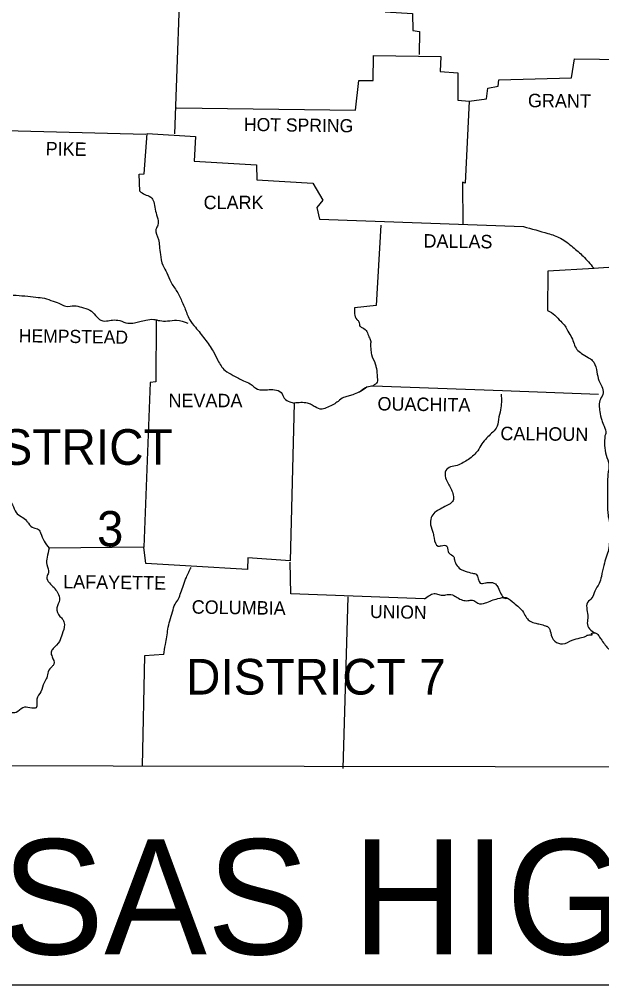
# Model space of a CAD drawing. Extents: x -2512 to 3792, y -435 to 2624.
# Drawn here: x 2800 to 2982.2, y 1364.9 to 1667 of the extents above; entities that cross this region are included whole.
import ezdxf

# ---------------------------------------------------------------- set-up
doc = ezdxf.new("R2010")
doc.units = 0
for name, color, linetype in [('1', 7, 'Continuous'), ('2', 7, 'Continuous'), ('3', 7, 'Continuous')]:
    doc.layers.add(name, color=color, linetype=linetype)

msp = doc.modelspace()

# ---------------------------------------------------------------- linework, layer by layer
at = {"layer": '1'}
for points in [[(2891.27, 1695.97), (2903.11, 1695.09), (2903.5, 1682.76), (2901.83, 1682.17), (2901.64, 1675.62), (2914.46, 1674.74), (2914.46, 1669.35), (2922.97, 1668.86), (2923.07, 1663.48), (2925.12, 1663.19), (2925.02, 1655.95)], [(2850.76, 1692.15), (2848.51, 1631.2)], [(2849.2, 1639.32), (2905.16, 1638.53), (2906.24, 1647.83), (2910.64, 1647.83), (2910.74, 1655.66), (2931.87, 1655.36), (2931.68, 1650.67), (2937.16, 1650.27), (2937.16, 1641.66), (2940.68, 1641.37)], [(2940.68, 1641.37), (2946.16, 1642.15), (2946.55, 1645.48), (2949.78, 1646.07), (2949.97, 1648.02), (2972.77, 1648.71), (2973.65, 1654.68), (2997.03, 1654.29)], [(2940.68, 1641.37), (2939.5, 1615.74), (2938.62, 1616.03), (2938.72, 1602.72)], [(2783.55, 1632.57), (2839.51, 1631.1)], [(2837.65, 1613.19), (2837.46, 1618.57), (2839.02, 1618.67), (2840, 1631.29), (2855.07, 1630.32), (2854.68, 1622.59), (2874.15, 1621.51), (2874.24, 1616.81), (2891.85, 1615.74), (2894.89, 1610.45), (2893.03, 1608.11), (2893.91, 1604.49), (2957.7, 1602.14)], [(2913.09, 1602.63), (2911.62, 1577.48), (2904.87, 1576.7)], [(2993.9, 1589.91), (2979.62, 1589.03)], [(2979.81, 1589.03), (2965.33, 1588.15), (2965.24, 1575.92)], [(2842.84, 1572.98), (2842.64, 1553.51), (2840.88, 1553.31), (2838.92, 1501.75)], [(2910.64, 1552.34), (2951.15, 1550.87), (2981.18, 1549.69)], [(2885.98, 1546.86), (2884.71, 1497.55), (2871.5, 1498.43), (2871.41, 1494.81), (2853.79, 1495.88)], [(2769.26, 1512.61), (2769.46, 1433.46), (3128.04, 1432.87)], [(2853.79, 1495.88), (2839.61, 1496.67), (2838.92, 1501.75), (2809.28, 1501.46)], [(2926.69, 1485.61), (2884.91, 1487.17), (2884.71, 1497.06)], [(2902.72, 1486.29), (2901.15, 1432.58)], [(2845.18, 1468.19), (2839.12, 1467.8), (2838.43, 1433.36)]]:
    msp.add_lwpolyline(points, dxfattribs=at)
for points in [[(2837.65, 1613.19), (2839.22, 1612.21), (2841.08, 1611.33), (2842.05, 1609.87), (2842.45, 1607.62), (2843.13, 1605.17), (2843.33, 1602.63), (2842.74, 1601.26), (2843.52, 1598.13), (2843.82, 1595.97), (2844.11, 1593.43), (2844.89, 1590.01), (2846.16, 1587.66), (2847.34, 1584.82), (2849.29, 1581.79), (2850.96, 1578.46), (2851.74, 1576.7), (2853.21, 1573.08), (2855.07, 1570.63), (2858, 1566.91), (2860.64, 1563.1), (2862.11, 1560.26), (2864.36, 1557.13), (2866.91, 1555.57), (2870.13, 1553.9), (2872.19, 1552.92), (2874.54, 1551.26), (2877.57, 1551.06), (2879.82, 1551.06), (2881.88, 1550.18), (2882.85, 1548.42), (2884.61, 1547.25), (2885.98, 1546.86)], [(2957.7, 1602.14), (2965.33, 1599.98), (2969.25, 1598.52), (2973.16, 1595.68), (2976.39, 1592.84), (2979.62, 1589.22)], [(2798.03, 1580.71), (2801.74, 1580.42), (2805.17, 1580.03), (2807.81, 1579.73), (2810.55, 1578.75), (2813, 1577.87), (2814.56, 1577.19), (2817.2, 1577.38), (2819.45, 1576.89), (2822, 1576.01), (2823.86, 1574.35), (2825.03, 1573.08), (2827.28, 1572.59), (2829.14, 1572.88), (2831.39, 1572.69), (2833.93, 1571.9), (2835.99, 1572), (2837.65, 1572.39), (2839.61, 1572.88), (2842.05, 1573.08), (2843.91, 1572.69), (2846.36, 1572.59), (2849.2, 1572.88), (2852.72, 1571.9)], [(2904.87, 1576.7), (2904.87, 1574.84), (2905.55, 1573.08), (2906.24, 1572.3), (2906.53, 1571.02), (2907.41, 1570.44), (2908.68, 1569.26), (2909.37, 1567.6), (2909.86, 1566.52), (2909.86, 1565.15), (2909.96, 1563.78), (2910.15, 1562.12), (2911.33, 1559.19), (2911.62, 1558.01), (2911.81, 1557.03), (2911.91, 1555.37), (2911.91, 1553.41), (2910.64, 1552.34)], [(2965.24, 1575.92), (2967.49, 1574.45), (2969.34, 1572.49), (2970.71, 1571.02), (2971.59, 1569.36), (2972.77, 1567.4), (2974.43, 1563.69), (2975.9, 1562.41), (2977.95, 1561.14), (2979.23, 1560.26), (2980.5, 1557.42), (2981.09, 1554.59), (2982.16, 1552.04), (2982.65, 1550.09), (2981.77, 1548.13), (2981.57, 1544.22), (2982.16, 1541.57), (2982.94, 1539.62), (2983.43, 1537.37), (2983.14, 1536.68)], [(2908.78, 1551.95), (2906.24, 1550.28), (2904.28, 1549.5), (2902.81, 1549.01), (2901.44, 1548.62), (2899.68, 1547.44), (2898.31, 1546.47), (2896.45, 1545.59), (2894.69, 1545), (2892.54, 1545.68), (2891.37, 1546.37), (2890.09, 1546.86), (2885.98, 1546.86)], [(2906.24, 1550.28), (2908.78, 1551.95), (2910.64, 1552.34)], [(2950.75, 1549.69), (2950.56, 1544.8), (2949.87, 1541.77), (2949.19, 1539.03), (2947.72, 1537.46), (2946.16, 1535.9), (2944.69, 1534.14), (2943.42, 1531.99), (2942.14, 1530.62), (2940.48, 1529.25), (2938.82, 1528.27), (2936.96, 1527.39), (2934.9, 1526.9), (2933.44, 1525.82), (2933.34, 1523.47), (2935, 1520.15), (2935.59, 1518.58), (2935.79, 1516.72), (2935.1, 1515.65), (2933.53, 1514.77), (2931.68, 1513.69), (2930.01, 1512.71), (2928.84, 1511.05), (2928.64, 1508.8), (2929.43, 1506.16), (2929.72, 1504.59), (2930.99, 1502.14), (2931.97, 1502.24), (2933.73, 1502.14), (2933.93, 1501.65), (2934.02, 1501.17), (2934.42, 1499.89), (2935.88, 1498.82), (2936.08, 1497.84), (2936.96, 1495.98), (2938.43, 1494.71), (2939.5, 1494.32), (2941.75, 1493.63), (2942.93, 1493.34), (2944.2, 1490.5), (2945.77, 1490.6), (2946.94, 1490.79), (2948.9, 1490.31), (2949.78, 1489.13), (2950.66, 1487.17), (2951.83, 1485.8), (2952.61, 1485.8)], [(2983.14, 1536.68), (2983.53, 1530.62), (2984.41, 1527.68), (2984.12, 1524.55), (2984.02, 1521.52), (2984.02, 1518.78), (2984.02, 1516.14), (2984.02, 1513.4), (2984.22, 1511.44), (2984.9, 1508.6), (2985.19, 1505.96), (2984.61, 1503.42), (2984.31, 1501.07), (2983.53, 1498.72), (2982.85, 1496.08), (2982.06, 1492.65), (2981.38, 1490.4), (2980.01, 1488.06), (2979.13, 1485.9), (2977.76, 1484.53), (2977.56, 1482.18), (2977.86, 1480.03), (2977.66, 1478.08), (2978.35, 1476.22), (2980.11, 1474.94)], [(2769.26, 1512.61), (2772.68, 1514.08), (2774.15, 1513.59), (2775.42, 1512.32), (2776.89, 1512.32), (2777.67, 1513.49), (2779.14, 1513.59), (2780.32, 1513.49), (2781.59, 1514.28), (2782.66, 1514.77), (2784.13, 1515.25), (2785.21, 1515.65), (2786.19, 1516.72), (2787.95, 1517.6), (2790, 1518.29), (2790.59, 1519.27), (2791.57, 1519.66), (2793.52, 1519.56), (2794.8, 1520.15), (2795.87, 1519.66), (2796.85, 1518.97), (2797.05, 1516.43), (2797.83, 1515.06), (2799, 1512.61), (2800.67, 1511.34), (2802.23, 1510.07), (2802.82, 1509.29), (2804.48, 1507.82), (2805.95, 1507.33), (2806.64, 1506.25), (2807.71, 1503.71), (2809.28, 1501.46)], [(2809.28, 1501.46), (2808.69, 1498.62), (2808.59, 1496.37), (2809.08, 1493.73), (2808.59, 1492.46), (2809.38, 1490.6), (2810.84, 1489.13), (2811.92, 1487.57), (2812.6, 1485.32), (2811.72, 1482.77), (2812.7, 1480.13), (2813.58, 1479.15), (2814.07, 1477.59), (2813.39, 1474.55), (2812.51, 1472.3), (2810.55, 1470.05), (2809.96, 1468.98), (2810.26, 1467.51), (2810.74, 1465.16), (2810.26, 1464.48), (2808.98, 1462.81), (2808.59, 1460.95), (2807.71, 1459.39), (2806.73, 1456.55), (2805.46, 1454.2), (2805.27, 1451.56), (2803.31, 1451.56), (2801.06, 1451.56), (2799, 1450.09), (2797.15, 1450), (2794.89, 1449.11), (2793.52, 1447.26), (2793.04, 1445.2), (2792.45, 1443.24), (2793.04, 1439.92), (2793.92, 1437.57), (2794.6, 1435.71), (2795.78, 1432.68)], [(2845.18, 1468.19), (2845.67, 1471.32), (2846.16, 1473.77), (2846.46, 1476.12), (2847.04, 1478.76), (2847.92, 1481.6), (2848.71, 1483.95), (2849.78, 1485.61), (2850.47, 1487.57), (2851.35, 1489.91), (2852.23, 1492.36), (2853.79, 1495.49)], [(2926.69, 1485.61), (2928.25, 1486.69), (2929.72, 1487.27), (2931.19, 1486.98), (2932.75, 1486.78), (2934.12, 1486.98), (2935.88, 1486.69), (2937.35, 1485.8), (2939.01, 1485.12), (2940.68, 1485.12), (2942.14, 1485.12), (2943.42, 1484.24), (2945.77, 1484.34), (2947.72, 1485.12), (2949.68, 1485.71), (2952.32, 1486), (2954.67, 1484.34), (2956.33, 1482.97), (2957.7, 1481.4), (2958.68, 1479.64), (2959.76, 1478.66), (2961.52, 1477.98), (2962.89, 1477.68), (2964.55, 1477.19), (2965.43, 1476.8), (2966.21, 1474.94), (2967.49, 1472.4), (2969.93, 1471.52), (2972.96, 1472.69), (2975.41, 1473.38), (2977.17, 1473.97), (2978.25, 1474.36), (2979.23, 1474.46), (2978.93, 1474.65), (2980.11, 1474.94), (2981.18, 1474.16), (2981.87, 1473.09), (2983.04, 1471.52), (2984.12, 1470.15), (2985.19, 1469.66), (2986.27, 1470.25), (2987.74, 1469.76), (2989.01, 1469.27), (2990.48, 1468.88), (2991.75, 1468.78), (2993.41, 1468.39), (2994.69, 1467.7), (2995.86, 1467.02), (2997.03, 1465.75), (2998.21, 1463.79), (2998.6, 1462.23), (2999.97, 1460.66), (3001.24, 1460.66), (3003.1, 1458.12), (3003.78, 1457.14), (3005.25, 1455.38), (3006.33, 1455.38), (3008.38, 1454.98)]]:
    msp.add_spline(points, degree=3, dxfattribs=at)
at = {"layer": '2'}
msp.add_line((2628.58, 1364.87), (3283.1, 1364.87), dxfattribs=at)

# ---------------------------------------------------------------- texts
for s, height, rotation, p in [('GRANT', 4.207, 359.4032, (2959.07, 1639.51)), ('HOT SPRING', 4.109, 359.2216, (2870.23, 1632.08)), ('PIKE', 4.206, 359.0452, (2808.2, 1624.44)), ('DALLAS', 4.206, 359.2462, (2926.39, 1595.58)), ('HEMPSTEAD', 4.108, 359.1885, (2799.79, 1565.94)), ('OUACHITA', 4.207, 359.2043, (2912.01, 1544.61)), ('CALHOUN', 4.207, 359.3634, (2950.46, 1535.31)), ('LAFAYETTE', 4.206, 359.1839, (2813.68, 1488.94)), ('COLUMBIA', 4.206, 359.2125, (2853.89, 1481.01)), ('UNION', 4.109, 358.9584, (2909.66, 1479.64))]:
    msp.add_text(s, height=height, rotation=rotation, dxfattribs=at).set_placement(p)
for s, height, p in [('CLARK', 4.207, (2857.63, 1607.59)), ('NEVADA', 4.207, (2846.65, 1545.59)), ('ARKANSAS HIGHWAY DISTRICT 2', 36, (2628.58, 1374.37))]:
    msp.add_text(s, height=height, dxfattribs=at).set_placement(p)
at = {"layer": '3'}
for s, height, p in [('DISTRICT', 11.154, (2779.19, 1527.57)), ('3', 11.06, (2824.3, 1502.04)), ('DISTRICT 7', 11.154, (2852.13, 1455.67))]:
    msp.add_text(s, height=height, dxfattribs=at).set_placement(p)

doc.saveas('drawing.dxf')
